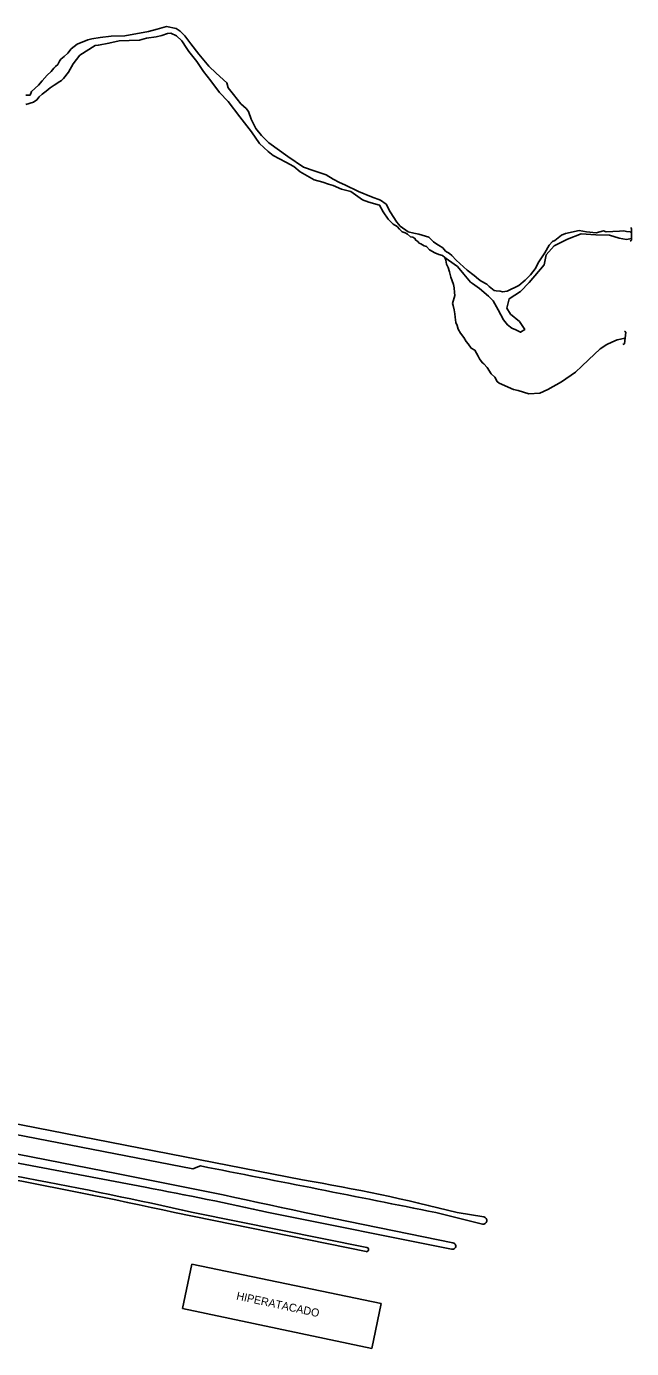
# Model space of a CAD drawing. Extents: x 325899 to 363134, y 7578590 to 7592502.
# Drawn here: x 344449 to 344752, y 7588434 to 7589095 of the extents above; entities that cross this region are included whole.
import ezdxf

# ---------------------------------------------------------------- set-up
doc = ezdxf.new("R2010")
doc.units = 0
for name, color, linetype in [('EDIFEXISTENT', 7, 'Continuous'), ('EDIFIDENTIF', 7, 'Continuous'), ('EDIFOBRAEXIS', 7, 'Continuous')]:
    doc.layers.add(name, color=color, linetype=linetype)

msp = doc.modelspace()

# ---------------------------------------------------------------- linework, layer by layer
at = {"layer": 'EDIFEXISTENT'}
for p, q in [((344751.35, 7588994.11), (344751.77, 7588993.48)), ((344751.77, 7588993.48), (344751.74, 7588987.7)), ((344751.74, 7588987.7), (344751.11, 7588987.31)), ((344748.27, 7588942.22), (344748.98, 7588941.76)), ((344748.98, 7588941.76), (344748.32, 7588935.98)), ((344748.32, 7588935.98), (344747.34, 7588935.56)), ((344527.43, 7588453.86), (344532.06, 7588476.09)), ((344532.06, 7588476.09), (344626.71, 7588456.36)), ((344626.71, 7588456.36), (344622.03, 7588433.92)), ((344622.03, 7588433.92), (344527.43, 7588453.86))]:
    msp.add_line(p, q, dxfattribs=at)
at = {"layer": 'EDIFOBRAEXIS'}
for points in [[(344449.05, 7589055.55), (344452.93, 7589056.68), (344454.65, 7589057.8), (344455.81, 7589059.33), (344457.33, 7589060.71), (344459.28, 7589062.16), (344461.26, 7589063.84), (344463.28, 7589065.22), (344466.17, 7589066.96), (344466.95, 7589067.49), (344467.96, 7589068.49), (344470.42, 7589071.69), (344472.74, 7589075.91), (344476.1, 7589080.19), (344483.77, 7589084.94), (344485.37, 7589085.25), (344490.59, 7589086.15), (344495.77, 7589087.26), (344500.66, 7589087.43), (344505.84, 7589087.68), (344509.39, 7589088.63), (344514.26, 7589089.41), (344517.13, 7589090), (344519.87, 7589091), (344521.57, 7589091.16), (344524.41, 7589089.82), (344527.04, 7589087.37), (344529.49, 7589083.5), (344530.63, 7589082.08), (344534.58, 7589077.07), (344537.8, 7589072.08), (344541.52, 7589067.32), (344545.81, 7589061.45), (344550.24, 7589057.1), (344556.1, 7589049.4), (344561.79, 7589041.83), (344565.89, 7589036.04), (344570.17, 7589031.96), (344572.72, 7589030.07), (344578.95, 7589026.77), (344583.09, 7589024.47), (344586.1, 7589021.89), (344593.12, 7589017.81), (344597.59, 7589016.78), (344600.41, 7589015.65), (344602.72, 7589015.07), (344606.86, 7589013.29), (344611.54, 7589012.08), (344617.26, 7589007.92), (344620.56, 7589006.76), (344625.85, 7589005.31), (344627.66, 7589001.91)], [(344449.19, 7589060.22), (344451.24, 7589060.23), (344452.02, 7589062.03), (344455.36, 7589065.14), (344457.26, 7589067.36), (344459.84, 7589070.13), (344461.73, 7589071.94), (344463.12, 7589073.75), (344464.01, 7589074.56), (344465.05, 7589075.56), (344465.9, 7589077.26), (344466.64, 7589078.18), (344468.26, 7589079.55), (344470.1, 7589081.23), (344471.77, 7589083.27), (344474.68, 7589085.62), (344480.11, 7589087.92), (344482.11, 7589088.33), (344486.24, 7589088.98), (344491.8, 7589089.71), (344498.63, 7589089.84), (344510.32, 7589092.03), (344514.73, 7589093.19), (344519.37, 7589094.53), (344524.27, 7589093.55), (344526.26, 7589092.12), (344528.55, 7589089.84), (344531.56, 7589085.81), (344535.51, 7589080.62), (344540.51, 7589074.65), (344544.2, 7589071.24), (344549.57, 7589066.36), (344550.29, 7589063.87), (344552.94, 7589060.56), (344556.46, 7589055.93), (344559.21, 7589053.52), (344560.38, 7589052.11), (344561.77, 7589048.18), (344563.99, 7589043.54), (344566.84, 7589040.05), (344570.61, 7589036.43), (344579.95, 7589029.56), (344587.79, 7589024.16), (344593.25, 7589022.32), (344599.22, 7589020.44), (344602.66, 7589018.3), (344605.81, 7589016.61), (344608.55, 7589015.4), (344615.34, 7589012.1), (344621.85, 7589009.45), (344626.25, 7589007.67), (344629.15, 7589005.65), (344631.16, 7589001.91)], [(344627.66, 7589001.91), (344630.11, 7588998.17), (344632.71, 7588995.71), (344634.57, 7588994.49), (344635.85, 7588993.16), (344637.18, 7588991.9), (344638.68, 7588991.33), (344639.78, 7588990.79), (344641.34, 7588989.48), (344642.48, 7588989.31), (344643.55, 7588988.61), (344644.02, 7588987.72), (344644.91, 7588987.12), (344645.71, 7588986.29), (344646.5, 7588985.84), (344648.13, 7588984.92), (344649.27, 7588984.52), (344650.81, 7588982.89), (344653.41, 7588981.44), (344655.42, 7588980.6), (344657.25, 7588980.13), (344658.53, 7588979.1), (344658.97, 7588977.76), (344659.27, 7588975.69), (344660.17, 7588974.07), (344660.72, 7588971.92), (344661.43, 7588969.21), (344662.88, 7588965.62), (344663.2, 7588963.93), (344663.38, 7588961.67), (344663.39, 7588960.17), (344662.29, 7588956.03), (344662.62, 7588955.04), (344663.05, 7588952.89), (344663.47, 7588950.87), (344663.64, 7588949.3), (344664.04, 7588946.56), (344664.62, 7588945.07), (344665.16, 7588943.27), (344666.35, 7588941.33), (344667.97, 7588939.16), (344669.13, 7588937.14), (344670.2, 7588935.86), (344671.64, 7588933.79), (344673.53, 7588932.74), (344675.13, 7588929.82), (344675.8, 7588928.48), (344677.06, 7588926.56), (344677.88, 7588925.91), (344679.59, 7588924.07), (344681.7, 7588920.97), (344683.39, 7588919.29), (344684.63, 7588917.09), (344685.67, 7588916.34), (344692.85, 7588913.18), (344695.19, 7588912.62), (344700.38, 7588910.94), (344705.98, 7588911.32), (344709.97, 7588913.13), (344716.84, 7588917.03), (344723.8, 7588921.83), (344726.91, 7588924.85), (344730.29, 7588927.93), (344736.15, 7588933.38), (344739.4, 7588935.59), (344741.87, 7588936.73), (344744.65, 7588937.9), (344748.65, 7588938.82)], [(344631.16, 7589001.91), (344634.41, 7588996.78), (344636.22, 7588994.78), (344640.18, 7588991.97), (344643, 7588991.27), (344645.46, 7588990.76), (344650.4, 7588989.2), (344652.88, 7588986.94), (344653.93, 7588986.01), (344655.23, 7588985.26), (344657.42, 7588983.84), (344658.88, 7588982.2), (344660.84, 7588981), (344661.92, 7588980.05), (344664.15, 7588977.71), (344669.7, 7588972.68), (344673.07, 7588970.1), (344675.32, 7588968.17), (344676.62, 7588967.29), (344679.37, 7588965.77), (344680.57, 7588964.54), (344683.18, 7588962.61), (344684.19, 7588962.34), (344686.07, 7588962.25), (344687.27, 7588961.94), (344689.55, 7588962.29), (344695.41, 7588965.13), (344698.6, 7588967.82), (344701.24, 7588970.48), (344703.53, 7588973.37), (344705.42, 7588976.99), (344708.42, 7588981.43), (344710.6, 7588985.28), (344712.31, 7588987.09), (344713.37, 7588987.58), (344716.79, 7588990.28), (344718.76, 7588991.08), (344725.65, 7588992.54), (344729.33, 7588991.84), (344734.05, 7588991.47), (344737.72, 7588992.37), (344739, 7588991.95), (344745.82, 7588992.31), (344747.92, 7588992.36), (344749.32, 7588991.99), (344751.02, 7588991.9), (344751.68, 7588991.3)], [(344658.53, 7588979.1), (344660.37, 7588977.8), (344664.76, 7588974.57), (344667.99, 7588970.77), (344671.27, 7588966.79), (344672.26, 7588966.16), (344675.76, 7588963.58), (344680.29, 7588959.69), (344682.67, 7588957.35), (344685.17, 7588952.89), (344687.77, 7588947.99), (344689.82, 7588945.45), (344691.92, 7588943.84), (344693.96, 7588942.9), (344696.25, 7588941.77), (344698.39, 7588943.11), (344695.85, 7588947.05), (344691.22, 7588950.79), (344689.42, 7588953.84), (344690.67, 7588958.47), (344696.32, 7588962.17), (344700.62, 7588966.65), (344708.1, 7588975.34), (344709.14, 7588980.44), (344713.14, 7588984.89), (344719.7, 7588988.3), (344726.53, 7588990.85), (344733.96, 7588990.48), (344740.81, 7588990.19), (344745.52, 7588988.81), (344749.28, 7588988.11), (344751.76, 7588988.64), (344751.76, 7588988.64)], [(344081.39, 7588616.99), (344358, 7588563), (344587.39, 7588518.2)], [(344081.39, 7588611.95), (344188.44, 7588590.67), (344194.18, 7588592.53), (344227.01, 7588585.62), (344231.7, 7588581.88), (344398.41, 7588549.76), (344532.63, 7588523.69), (344536.32, 7588525.15)], [(344081.39, 7588601.32), (344380.07, 7588543.64), (344495.24, 7588521.26)], [(344081.39, 7588596.62), (344349.77, 7588544.51), (344508.81, 7588514.53)], [(344081.39, 7588591.48), (344292.8, 7588549.42), (344449.41, 7588519.04)], [(344619.11, 7588482.34), (344523.38, 7588501.91)], [(344532.64, 7588501.91), (344619.42, 7588484.41)], [(344661.86, 7588483.64), (344570.42, 7588501.91)], [(344588.32, 7588501.91), (344662.53, 7588486.75)], [(344677.24, 7588496.01), (344653.9, 7588501.91)], [(344664.55, 7588501.91), (344677.95, 7588499.73)]]:
    msp.add_lwpolyline(points, dxfattribs=at)
for centre, radius, start, end in [((339322.89, 7561831.2), 27198.28, 78.696528, 78.949009), ((343938.48, 7585827.48), 2737.65, 77.66367, 79.67071), ((344058.17, 7586406.62), 2148.34, 77.24079, 79.50709), ((343726.83, 7584591.11), 4004.57, 77.57705, 78.93735), ((344428.6, 7587574.99), 956.48, 75.71843, 80.44361), ((344133.32, 7586524.4), 2025.24, 77.53626, 79.31529), ((344677.53, 7588497.88), 1.9, 261.2262, 77.2881), ((344619.28, 7588483.37), 1.05, 260.80747, 82.27115), ((344662.32, 7588485.17), 1.6, 253.55639, 82.4432)]:
    msp.add_arc(centre, radius, start, end, dxfattribs=at)

# ---------------------------------------------------------------- texts
at = {"layer": 'EDIFIDENTIF'}
msp.add_text('HIPERATACADO', height=4, rotation=347.82969, dxfattribs=at).set_placement((344554.05, 7588458.47))

doc.saveas('drawing.dxf')
